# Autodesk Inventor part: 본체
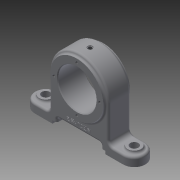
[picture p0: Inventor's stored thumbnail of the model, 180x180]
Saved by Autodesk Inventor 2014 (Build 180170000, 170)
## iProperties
Created: 2019-05
Part Number: 본체
Material: Generic
Document SubType Name: Modeling
Designer: kh
Density: 1 g/cm^3
Appearance: Default
Mass: 168.409 g
Surface Area: 319.309 cm^2
Volume: 168.409 cm^3
Author: kh
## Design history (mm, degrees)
sketch "스케치1"
  geometry: L1 (-60, 0)-(60, 0); L2 (-60, -15)-(60, -15); L3 (60, 15)-(-60, 15); A1 r 15 centre (-60, 0) between (-60, 15) and (-60, -15); A2 r 15 centre (60, 0) between (60, -15) and (60, 15); 1 further point
  constraints: 8 end point, 4 point on circle, 4 tangent, 2 centre point, 1 horizontal, 1 midpoint, 1 parallel
  dimensions: "d0" = 60 distance of point (0, 0) L1.end; "d1" = 30 diameter of A2
extrude "돌출1" new body sketch "스케치1" distance "d2" = 12; taper "d3" = 0 deg
sketch "스케치2"
  geometry: C1 r 9 at (-60, 0); C2 r 9 at (60, 0); A1 r 15 centre (-60, 0) between (-60, 15) and (-60, -15) reference; A2 r 15 centre (60, 0) between (60, -15) and (60, 15) reference; 1 further point
  constraints: 2 centre point, 2 coincident
  dimensions: "d4" = 18 diameter of C1; "d5" = 18 diameter of C2
extrude "돌출2" join sketch "스케치2" distance "d6" = 3; taper "d7" = 0 deg
sketch "스케치3"
  geometry: L1 (-40, -15)-(40, -15); L2 (40, -15)-(40, 15); L3 (40, 15)-(-40, 15); L4 (-40, 15)-(-40, -15); L5 (-40, -15)-(40, 15); L6 (40, -15)-(-40, 15); L7 (60, 15)-(-60, 15) reference; 1 further point
  constraints: 12 end point, 2 midpoint, 2 parallel, 1 collinear, 1 horizontal, 1 perpendicular
  dimensions: "d8" = 80 distance between parallel lines of L2 L4
extrude "돌출3" join sketch "스케치3" distance "d9" = 88; taper "d10" = 0 deg
fillet "모깎기1" dims "d11" = 40
sketch "스케치4"
  geometry: C1 r 36 at (0, 60); A1 r 40 centre (0, 60) between (40, 60) and (-40, 60) reference; 1 further point
  constraints: 1 centre point, 1 coincident
  dimensions: "d12" = 72 diameter of C1
extrude "돌출4" join sketch "스케치4" stored distance "d13" = 36; taper "d14" = 0 deg
hole "구멍1" diameter "d17" = 52; stored, may be unused: countersink angle "d21" = 90 deg, drill point angle "d23" = 118 deg; dims "d15" = 10, "d16" = 10, "d18" = 6, "d19" = 4, "d20" = 2, "d22" = 8
hole "구멍2" diameter "d26" = 11; stored, may be unused: countersink angle "d30" = 90 deg, drill point angle "d32" = 118 deg; dims "d24" = 10, "d25" = 10, "d27" = 6, "d28" = 4, "d29" = 2, "d31" = 8
hole "구멍3" diameter "d35" = 11; stored, may be unused: countersink angle "d39" = 90 deg, drill point angle "d41" = 118 deg; dims "d33" = 10, "d34" = 10, "d36" = 6, "d37" = 4, "d38" = 2, "d40" = 8
sketch "스케치5"
  geometry: L1 (0, 0)-(0, 31); C1 r 26 at (0, 0) reference; 2 further points
  constraints: 2 end point, 1 coincident, 1 vertical
  dimensions: "d42" = 31 distance of L1.start L1.end
hole "구멍4" sketch "스케치5" at (0, 31) diameter "d43" = 3.459; stored, may be unused: countersink angle "d47" = 90 deg, drill point angle "d49" = 118 deg; dims "d44" = 6, "d45" = 4, "d46" = 2, "d48" = 8
node "작업 평면1"
sketch "스케치6"
  geometry: 2 further points
  constraints: 1 coincident
hole "구멍5" sketch "스케치6" diameter "d53" = 5.459; stored, may be unused: countersink angle "d57" = 90 deg, drill point angle "d59" = 118 deg; dims "d54" = 8, "d55" = 7, "d56" = 1, "d58" = 10
hole "구멍6" sketch "스케치6" diameter "d60" = 2; stored, may be unused: countersink angle "d64" = 90 deg, drill point angle "d66" = 0 deg; dims "d61" = 2, "d62" = 7, "d63" = 1, "d65" = 10
sketch "스케치10"
  geometry: L1 (0, 0)-(0, 34); 2 further points
  constraints: 2 end point, 1 point on line, 1 vertical, 1 vertical alignment, 1 other
hole "구멍7" sketch "스케치10" at (0, 26) diameter "d81" = 3; stored, may be unused: countersink angle "d85" = 90 deg, drill point angle "d87" = 118 deg; dims "d82" = 3, "d83" = 7, "d84" = 1, "d86" = 10
chamfer "모따기1" distance "d67" = 1; stored, may be unused: second distance "d68" = 2, angle "d69" = 45 deg
fillet "모깎기2" dims "d70" = 3, "d88" = 6
sketch "스케치7"
  geometry: L1 (-36, -15)-(36, -15); L2 (36, -15)-(36, 15); L3 (36, 15)-(-36, 15); L4 (-36, 15)-(-36, -15); L5 (-36, -15)-(36, 15); L6 (36, -15)-(-36, 15); L7 (-60, 15)-(60, 15) reference; 1 further point
  constraints: 12 end point, 2 midpoint, 2 parallel, 1 collinear, 1 horizontal, 1 perpendicular
  dimensions: "d71" = 72 distance between parallel lines of L2 L4
extrude "돌출5" cut sketch "스케치7" distance "d72" = 4; taper "d73" = 0 deg
sketch "스케치8"
  geometry: L1 (-30, -15)-(30, -15); L2 (30, -15)-(30, 15); L3 (30, 15)-(-30, 15); L4 (-30, 15)-(-30, -15); L5 (-30, -15)-(30, 15); L6 (30, -15)-(-30, 15); L7 (-36, 15)-(36, 15) reference; 1 further point
  constraints: 12 end point, 2 midpoint, 2 parallel, 1 collinear, 1 horizontal, 1 perpendicular
  dimensions: "d74" = 60 distance between parallel lines of L2 L4
extrude "돌출6" cut sketch "스케치8" distance "d75" = 6; taper "d76" = 0 deg
sketch "스케치9"
  geometry: L1 (-20.261, -40.598)-(20.261, -40.598); L2 (20.261, -40.598)-(20.261, -45.402); L3 (20.261, -45.402)-(-20.261, -45.402); L4 (-20.261, -45.402)-(-20.261, -40.598); L5 (-20.261, -43)-(20.261, -43); L6 (0, -40.598)-(0, -45.402); L7 (-30, -50)-(30, -50) reference; 1 further point
  constraints: 4 end point, 4 midpoint, 1 point on line, 2 other
  dimensions: "d77" = 7 distance between parallel lines of L7 L5
feature "엠보싱1" sketch "스케치9" dims "d0" = 60, "d1" = 30, "d8" = 80, "d78" = 0.5, "d79" = 0
fillet "모깎기3" dims "d80" = 3
node "솔리드1"
pattern_circular "원형 패턴1" dims angle "d51" = 360 deg
mirror "대칭1"
